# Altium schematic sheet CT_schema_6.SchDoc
size 334 x 183 mm
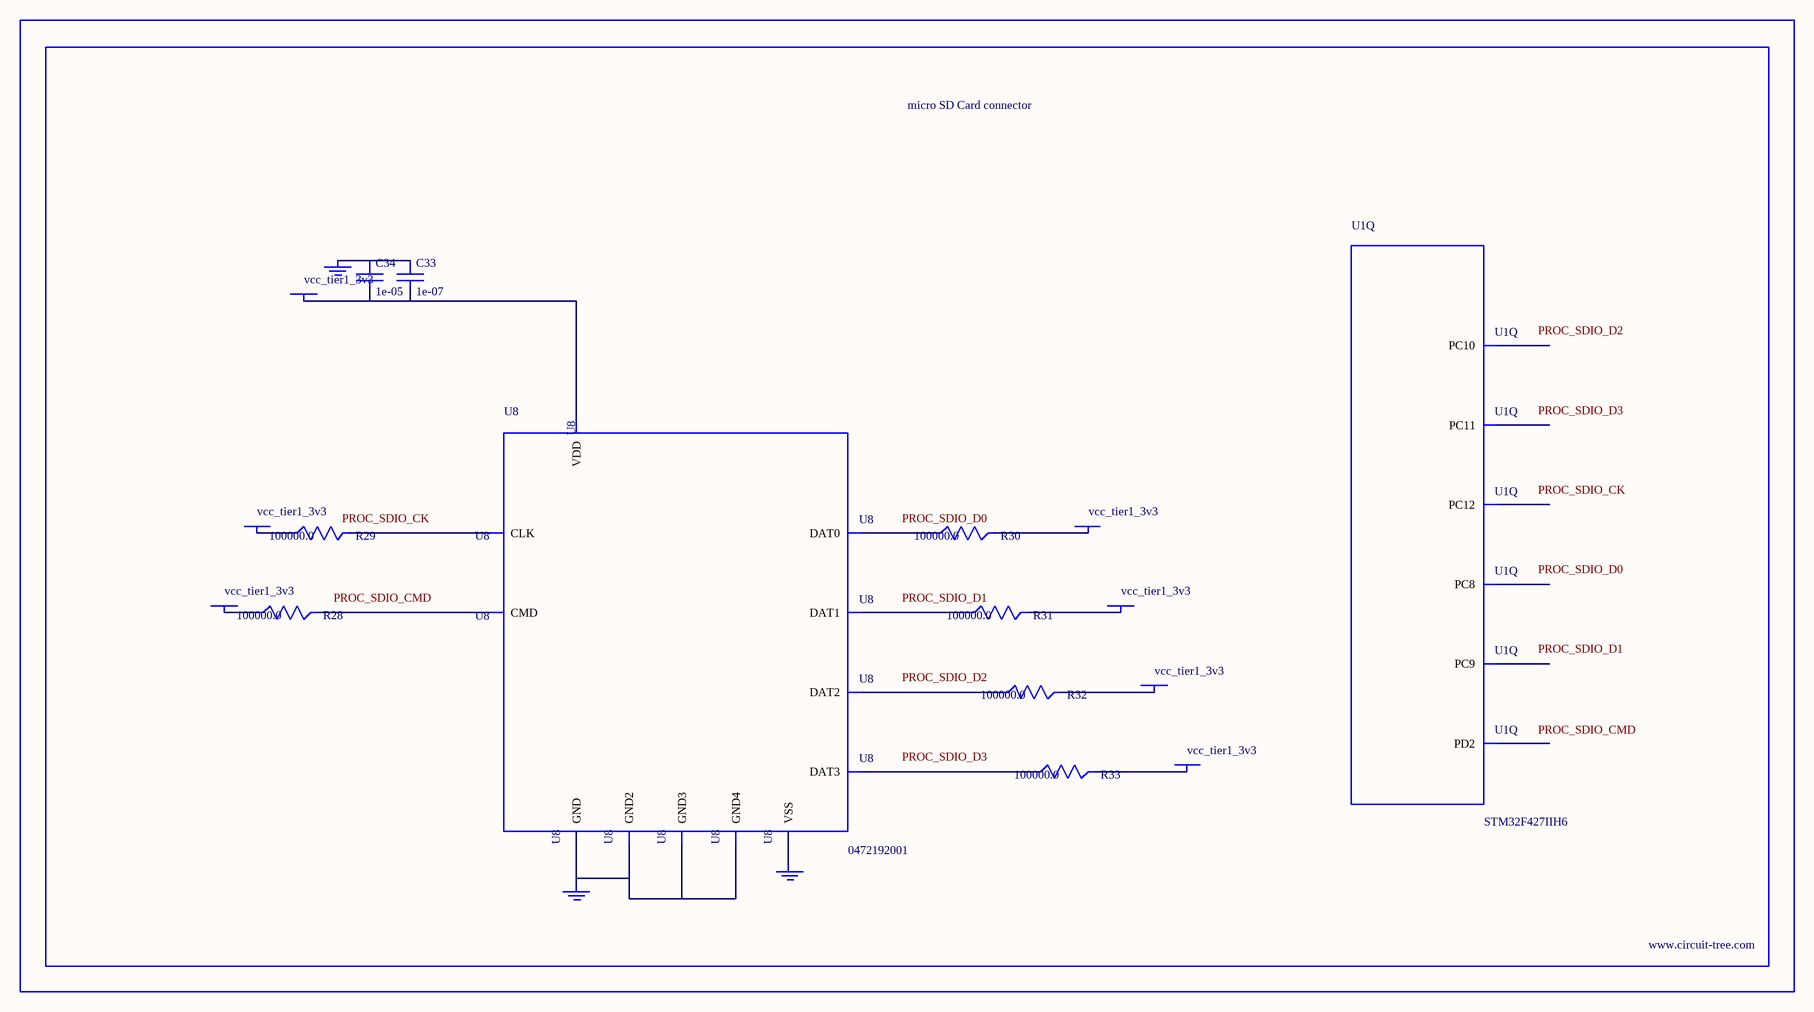
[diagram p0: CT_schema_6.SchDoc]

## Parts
BORDER5  (no value)
C33  1e-07  [C0402]
C34  1e-05  [C0805]
GND_INSTANCE_5_0  (no value)
GND_INSTANCE_5_1  (no value)
GND_INSTANCE_5_2  (no value)
POWER_INSTANCE_5_0  vcc_tier1_3v3
POWER_INSTANCE_5_1  vcc_tier1_3v3
POWER_INSTANCE_5_2  vcc_tier1_3v3
POWER_INSTANCE_5_3  vcc_tier1_3v3
POWER_INSTANCE_5_4  vcc_tier1_3v3
POWER_INSTANCE_5_5  vcc_tier1_3v3
POWER_INSTANCE_5_6  vcc_tier1_3v3
R28  100000.0  [R0603]
R29  100000.0  [R0603]
R30  100000.0  [R0603]
R31  100000.0  [R0603]
R32  100000.0  [R0603]
R33  100000.0  [R0603]
U1  STM32F427IIH6  [UFBGA176_25]  (part Q of 17)
U8  0472192001  [MOLEX_47219-2001]

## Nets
NetC33_1: C33.1 C34.1 GND_INSTANCE_5_0.0(GND)
NetC33_2: C33.2 C34.2 POWER_INSTANCE_5_3.0(PWR) U8.4(VDD)
NetGND_INSTANCE_5_1_0: GND_INSTANCE_5_1.0(GND) U8.6(VSS)
NetGND_INSTANCE_5_2_0: GND_INSTANCE_5_2.0(GND) U8.G1(GND) U8.G2(GND2) U8.G3(GND3) U8.G4(GND4)
NetPOWER_INSTANCE_5_0_0: POWER_INSTANCE_5_0.0(PWR) R32.2
NetPOWER_INSTANCE_5_1_0: POWER_INSTANCE_5_1.0(PWR) R33.2
NetPOWER_INSTANCE_5_2_0: POWER_INSTANCE_5_2.0(PWR) R28.1
NetPOWER_INSTANCE_5_4_0: POWER_INSTANCE_5_4.0(PWR) R29.1
NetPOWER_INSTANCE_5_5_0: POWER_INSTANCE_5_5.0(PWR) R30.2
NetPOWER_INSTANCE_5_6_0: POWER_INSTANCE_5_6.0(PWR) R31.2
NetR28_2: R28.2 U8.3(CMD)
NetR29_2: R29.2 U8.5(CLK)
NetR30_1: R30.1 U8.7(DAT0)
NetR31_1: R31.1 U8.8(DAT1)
NetR32_1: R32.1 U8.1(DAT2)
NetR33_1: R33.1 U8.2(DAT3)

Not connected (* = marked no-connect by the designer): U1 A12(PC12) B13(PC11) B14(PC10) D12(PD2) F14(PC9) G14(PC8)

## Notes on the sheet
- Labels drawn without touching a wire or pin: PROC_SDIO_CK, PROC_SDIO_CMD, PROC_SDIO_D0, PROC_SDIO_D1, PROC_SDIO_D2, PROC_SDIO_D3

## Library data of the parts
BORDER5 = BORDER_PAGE5
C33 = C0402C104K3RACTU
C34 = C0805C106K8RACTU
GND_INSTANCE_5_0-GND_INSTANCE_5_2 = GND
POWER_INSTANCE_5_0-POWER_INSTANCE_5_6 = PWR
R28-R33 = RC0603JR-07100KL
